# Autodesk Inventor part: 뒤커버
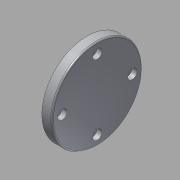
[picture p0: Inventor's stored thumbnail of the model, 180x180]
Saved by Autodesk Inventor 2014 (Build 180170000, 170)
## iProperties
Created: 2015-09
Part Number: 뒤커버
Material: 알루미늄 6061
Document SubType Name: Modeling
Designer: mduedu
Density: 2.71 g/cm^3
Mass: 54.0417 g
Surface Area: 84.9688 cm^2
Volume: 19.9416 cm^3
Appearance: 알루미늄 - 평지
Author: mduedu
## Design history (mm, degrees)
sketch "스케치1"
  geometry: L1 (-15.5, 47)-(-15.5, 78); L2 (-15.5, 78)-(-22.5, 78); L3 (-22.5, 78)-(-22.5, 67); L4 (-25.5, 67)-(-25.5, 47); L5 (-79.5, 39.5)-(-79.5, 54.5) reference; L6 (48.5, 54.5)-(48.5, 39.5) reference; L7 (-79.5, 47)-(48.5, 47); L8 (-22.5, 67)-(-25.5, 67); L9 (-25.5, 47)-(-15.5, 47); 1 further point
  constraints: 14 end point, 4 midpoint, 3 parallel, 1 collinear, 1 point on line, 1 vertical
  dimensions: "d6" = 62 diameter of L2 L7; "d7" = 7 distance of L1.end L2.end; "d8" = 40 diameter of L3.end L7; "d32" = 10 distance between parallel lines of L1 L4
revolve "회전1" sketch "스케치1" stored, may be unused: angle "d4" = 90 deg
sketch "스케치4"
  geometry: C1 r 31 at (0, 0) reference; 2 further points
  constraints: 1 coincident
hole "구멍3" sketch "스케치4" at (0, 0) diameter "d33" = 33; stored, may be unused: countersink angle "d37" = 90 deg, drill point angle "d39" = 0 deg; dims "d34" = 6, "d35" = 4, "d36" = 2, "d38" = 5
fillet "모깎기4" dims "d40" = 1
chamfer "모따기2" distance "d41" = 1; stored, may be unused: second distance "d42" = 2, angle "d43" = 45 deg
sketch "스케치5" dims "d44" = 48
  geometry: C1 r 31 at (0, 0) reference; 6 further points
  constraints: 2 vertical alignment, 1 coincident, 7 other
  dimensions: "d47" = 360 deg dimension on C1.centre point (0, -24) (derived)
sketch "스케치6"
  geometry: 4 further points
hole "구멍4" sketch "스케치6" at (24, 0), (0, 24), (-24, 0), (0, -24) diameter "d49" = 3.4; stored, may be unused: countersink angle "d53" = 90 deg, drill point angle "d55" = 0 deg; dims "d50" = 6, "d51" = 6.5, "d52" = 3.4, "d54" = 8
node "솔리드1"
node "참조1"
node "참조2"
